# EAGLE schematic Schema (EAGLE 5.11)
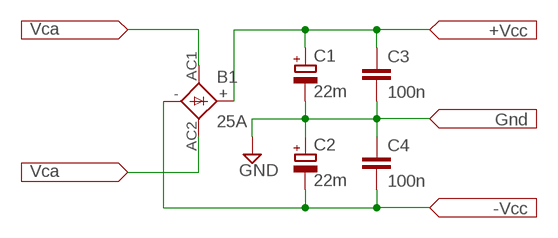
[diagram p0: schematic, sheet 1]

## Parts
B1  25A  S41  [S41]
C1  22m  CPOL-EUE10-35  [EB35D]
C2  22m  CPOL-EUE10-35  [EB35D]
C3  100n  C-EU050-025X075  [C050-025X075]
C4  100n  C-EU050-025X075  [C050-025X075]

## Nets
GND: C1.- C2.+ C3.2 C4.1
N$1: B1.AC2
N$2: B1.AC1
N$3: B1.- C2.- C4.2
N$4: B1.+ C1.+ C3.1

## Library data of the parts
B1 = rectifier:S41: SEMIKRON RECTIFIER
C1 C2 = resistor:CPOL-EU: POLARIZED CAPACITOR, European symbol
C3 C4 = resistor:C-EU: CAPACITOR, European symbol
